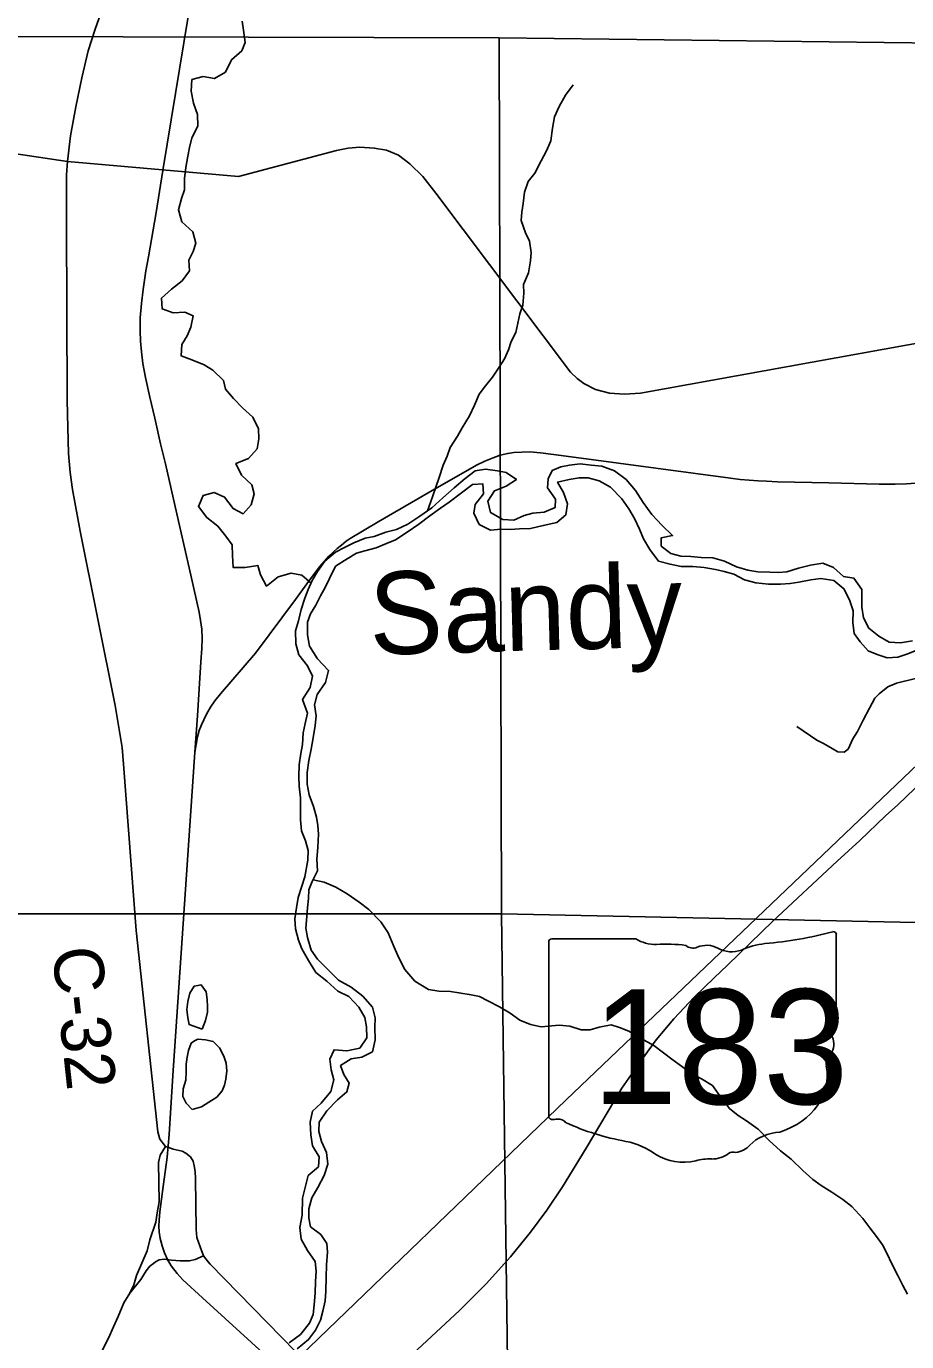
# Model space of a CAD drawing. Extents: x 0 to 34, y 0 to 22.
# Drawn here: x 2.706 to 3.716, y 15.037 to 16.545 of the extents above; entities that cross this region are included whole.
import ezdxf

# ---------------------------------------------------------------- set-up
doc = ezdxf.new("R2010")
doc.units = 0
doc.layers.add('Default', color=7, linetype='Continuous')

msp = doc.modelspace()

# ---------------------------------------------------------------- linework, layer by layer
at = {"layer": 'Default'}
for p, q in [((3.3055, 15.4951), (3.3055, 15.295)), ((3.4053, 15.4986), (3.3088, 15.4986)), ((3.6351, 15.3988), (3.6351, 15.5035)), ((3.6351, 15.3989), (3.6351, 15.3988))]:
    msp.add_line(p, q, dxfattribs=at)
for points in [[(2.7536, 16.3903), (2.7572, 16.4197), (2.7633, 16.4531), (2.77, 16.4862), (2.7773, 16.5171), (2.7854, 16.5419), (2.7952, 16.5699), (2.7994, 16.5866), (2.801, 16.5991), (2.8016, 16.6128), (2.8007, 16.6763), (2.7997, 16.8054), (2.7985, 16.9091), (2.7987, 16.9258), (2.8, 16.9356), (2.8021, 16.9437), (2.8053, 16.952), (2.8092, 16.9585), (2.8142, 16.9649), (2.8306, 16.9836), (2.8489, 17.0057), (2.8565, 17.0154)], [(2.9776, 15.0237), (2.9083, 15.0868), (2.8858, 15.1074), (2.8792, 15.1148), (2.8725, 15.1235), (2.8684, 15.1307), (2.8648, 15.1384), (2.8621, 15.1464), (2.8598, 15.1549), (2.8589, 15.1626), (2.8582, 15.1693), (2.8586, 15.176), (2.8596, 15.1856), (2.8627, 15.2088), (2.8679, 15.2483), (2.8701, 15.2744), (2.8744, 15.342), (2.8871, 15.5273), (2.8995, 15.7129), (2.9027, 15.7545), (2.9065, 15.8165), (2.9078, 15.8316), (2.9079, 15.8433), (2.9075, 15.8537), (2.9062, 15.8638), (2.9044, 15.8735), (2.8951, 15.9157), (2.879, 15.986), (2.8658, 16.0435), (2.8602, 16.0664), (2.8536, 16.096), (2.8481, 16.12), (2.8431, 16.1426), (2.8401, 16.1584), (2.8383, 16.1721), (2.8374, 16.1843), (2.8368, 16.1959), (2.837, 16.2108), (2.8386, 16.2275), (2.8405, 16.2436), (2.8435, 16.2647), (2.8465, 16.281), (2.8552, 16.3316), (2.8628, 16.3799), (2.887, 16.5264), (2.936, 16.8224)], [(3.0328, 15.9067), (3.0221, 15.9157), (3.01, 15.9182), (2.9953, 15.9138), (2.9819, 15.9033), (2.9749, 15.9161), (2.9717, 15.927), (2.9573, 15.9245), (2.9434, 15.9247), (2.9428, 15.9383), (2.9426, 15.9504), (2.9352, 15.9605), (2.926, 15.9721), (2.9133, 15.9818), (2.9037, 15.9945), (2.9091, 16.0071), (2.9219, 16.0107), (2.9337, 16.0053), (2.9434, 15.9921), (2.9552, 15.9863), (2.9641, 15.9966), (2.9677, 16.0092), (2.9649, 16.0194), (2.953, 16.0306), (2.9467, 16.0438), (2.961, 16.0497), (2.971, 16.0608), (2.9731, 16.0722), (2.9725, 16.0836), (2.9662, 16.0971), (2.9543, 16.1079), (2.9439, 16.1184), (2.9347, 16.1292), (2.9323, 16.139), (2.9204, 16.151), (2.9104, 16.1569), (2.8963, 16.1627), (2.8838, 16.1674), (2.8847, 16.1804), (2.891, 16.1903), (2.895, 16.2002), (2.8978, 16.2132), (2.8883, 16.2176), (2.8747, 16.2166), (2.8621, 16.2213), (2.8612, 16.2334), (2.8727, 16.2438), (2.885, 16.2535), (2.8935, 16.265), (2.8929, 16.2772), (2.8977, 16.2871), (2.9009, 16.2966), (2.8973, 16.3094), (2.8847, 16.321), (2.8807, 16.335), (2.8842, 16.3479), (2.8878, 16.3578), (2.8876, 16.3707), (2.8893, 16.3832), (2.8917, 16.3965), (2.8935, 16.4064), (2.8963, 16.4175), (2.9029, 16.4308), (2.9027, 16.4441), (2.8979, 16.4573), (2.8954, 16.4709), (2.8963, 16.4842), (2.9091, 16.4878), (2.922, 16.4854), (2.9347, 16.4928), (2.9417, 16.5069), (2.9536, 16.5173), (2.9572, 16.5269), (2.9555, 16.5409), (2.9538, 16.5511)], [(2.1, 16.5331), (2.1344, 16.5325), (2.2208, 16.5334), (2.2952, 16.5341), (2.3308, 16.5333), (2.3532, 16.5318), (2.3617, 16.531), (2.3692, 16.5283), (2.393, 16.5144), (2.5498, 16.4286), (2.566, 16.4206), (2.5709, 16.418), (2.6047, 16.4125), (2.7536, 16.3903)], [(3.1662, 15.9895), (3.1722, 16.0057), (3.1758, 16.0168), (3.1798, 16.0278), (3.1844, 16.042), (3.1888, 16.0523), (3.1924, 16.0622), (3.2009, 16.0752), (3.206, 16.0848), (3.2145, 16.0985), (3.2203, 16.1108), (3.2258, 16.1234), (3.2328, 16.133), (3.241, 16.143), (3.2487, 16.1545), (3.2546, 16.164), (3.2594, 16.1743), (3.2622, 16.1839), (3.2677, 16.1942), (3.2698, 16.2048), (3.2723, 16.2155), (3.2755, 16.2254), (3.2768, 16.2394), (3.2763, 16.2493), (3.2821, 16.2627), (3.2845, 16.2763), (3.2851, 16.2858), (3.2834, 16.2987), (3.2787, 16.3085), (3.2739, 16.3224), (3.2745, 16.3323), (3.2759, 16.3422), (3.2775, 16.3551), (3.2819, 16.3673), (3.2893, 16.3769), (3.2966, 16.391), (3.3028, 16.4025), (3.3079, 16.414), (3.3096, 16.4284), (3.312, 16.4413), (3.3175, 16.4532), (3.3245, 16.4662), (3.3333, 16.4781)], [(2.7536, 16.3903), (2.9496, 16.3731), (3.0622, 16.4028), (3.0755, 16.4054), (3.0886, 16.4068), (3.1054, 16.4056), (3.1194, 16.4032), (3.1332, 16.3974), (3.1463, 16.3874), (3.161, 16.3732), (3.1758, 16.3541), (3.3304, 16.1487), (3.3378, 16.1413), (3.3458, 16.1357), (3.3589, 16.1287), (3.3749, 16.1245), (3.3922, 16.1234), (3.4105, 16.1244), (3.9144, 16.2154), (3.9245, 16.2165), (3.9335, 16.2176), (4.1665, 16.2407)], [(2.8685, 15.2596), (2.8659, 15.2606), (2.8595, 15.269), (2.8571, 15.2774), (2.8325, 15.5081), (2.8177, 15.6989), (2.8161, 15.7182), (2.8084, 15.7663), (2.7681, 15.9661), (2.7595, 16.014), (2.7566, 16.0335), (2.7547, 16.0552), (2.7538, 16.085), (2.7532, 16.1166), (2.7523, 16.3202), (2.7526, 16.375), (2.7536, 16.3903)], [(2.8995, 15.7129), (2.9025, 15.7305), (2.9047, 15.7377), (2.9072, 15.7441), (2.9098, 15.7499), (2.9131, 15.7565), (2.9177, 15.7645), (2.9227, 15.7718), (2.9292, 15.7795), (2.969, 15.8264), (3.015, 15.8878), (3.0312, 15.9101), (3.0428, 15.9258), (3.0479, 15.9316), (3.0533, 15.9374), (3.0581, 15.942), (3.0628, 15.9462), (3.0678, 15.9503), (3.0733, 15.9547), (3.0778, 15.958), (3.1098, 15.977), (3.167, 16.0101), (3.2225, 16.0418), (3.2323, 16.0466), (3.2415, 16.0504), (3.2496, 16.0534), (3.2583, 16.0554), (3.2655, 16.0564), (3.2745, 16.0569), (3.2838, 16.0571), (3.2958, 16.056), (3.3108, 16.0542), (3.3425, 16.0501), (3.5139, 16.027), (3.5249, 16.0257), (3.5351, 16.0246), (3.5454, 16.0241), (3.555, 16.0235), (3.5677, 16.0229), (3.6264, 16.0217), (3.6842, 16.0203), (3.7025, 16.0202), (3.7156, 16.0206), (3.7263, 16.0214)], [(3.3191, 16.04), (3.3093, 16.0357), (3.3049, 16.0261), (3.304, 16.0159), (3.3133, 16.0028), (3.3127, 15.9933), (3.3003, 15.9882), (3.2871, 15.9868), (3.2773, 15.9844), (3.2653, 15.9788), (3.2528, 15.9798), (3.2387, 15.9875), (3.2355, 16.0007), (3.2432, 16.0126), (3.2567, 16.0177), (3.2683, 16.0255), (3.2564, 16.0337), (3.2466, 16.0354), (3.2329, 16.0374), (3.2209, 16.0353), (3.2097, 16.0268), (3.197, 16.016), (3.184, 16.0044), (3.1713, 15.9932), (3.1575, 15.9835), (3.1437, 15.9741), (3.131, 15.9682), (3.1185, 15.965), (3.1054, 15.9602), (3.0949, 15.9582), (3.0821, 15.953), (3.0712, 15.9475), (3.0607, 15.942), (3.0488, 15.932), (3.0403, 15.9201), (3.0341, 15.9097), (3.0297, 15.8994), (3.0257, 15.8895), (3.0214, 15.8765), (3.0183, 15.8636), (3.0151, 15.8518), (3.0153, 15.837), (3.0189, 15.8246), (3.0286, 15.8118), (3.0345, 15.7998), (3.0317, 15.7869), (3.0232, 15.7731), (3.0288, 15.7576), (3.0263, 15.7458), (3.0239, 15.7348), (3.023, 15.7215), (3.0212, 15.7112), (3.0192, 15.6983), (3.0187, 15.685), (3.0192, 15.6737), (3.0206, 15.6604), (3.0208, 15.6475), (3.0207, 15.635), (3.022, 15.6225), (3.0264, 15.6112), (3.0296, 15.5999), (3.029, 15.5889), (3.0256, 15.5699), (3.0223, 15.5592), (3.018, 15.5459), (3.016, 15.5341), (3.0143, 15.5216), (3.0149, 15.5102), (3.0185, 15.497), (3.0221, 15.4872), (3.0298, 15.4737), (3.0384, 15.4602), (3.051, 15.4501), (3.0637, 15.4386), (3.0763, 15.4324), (3.0878, 15.4204), (3.0945, 15.4084), (3.0965, 15.3978), (3.0967, 15.3853), (3.0886, 15.3734), (3.0739, 15.3702), (3.0592, 15.3714), (3.0545, 15.3607), (3.0558, 15.3486), (3.059, 15.3369), (3.0555, 15.3236), (3.0444, 15.3101), (3.0347, 15.3012), (3.0319, 15.2883), (3.0325, 15.2739), (3.0346, 15.2614), (3.042, 15.2487), (3.0415, 15.2373), (3.0295, 15.2272), (3.0232, 15.2013), (3.0228, 15.1816), (3.02, 15.1675), (3.0217, 15.1543), (3.0287, 15.1411), (3.0376, 15.1284), (3.0386, 15.1174)], [(3.7223, 15.8406), (3.7087, 15.8381), (3.6959, 15.839), (3.684, 15.846), (3.6725, 15.8549), (3.6663, 15.8669), (3.6642, 15.879), (3.6644, 15.8893), (3.6642, 15.8995), (3.6553, 15.9122), (3.6432, 15.9143), (3.632, 15.9247), (3.6195, 15.9295), (3.6056, 15.9273), (3.5916, 15.9237), (3.5785, 15.9197), (3.5687, 15.9187), (3.5588, 15.9193), (3.5452, 15.9195), (3.5335, 15.9216), (3.5206, 15.9255), (3.5068, 15.9317), (3.4935, 15.9357), (3.4803, 15.9362), (3.4682, 15.9371), (3.4569, 15.9377), (3.4455, 15.9406), (3.4344, 15.9491), (3.4342, 15.9586), (3.4474, 15.9611), (3.4355, 15.9726), (3.4235, 15.9853), (3.4135, 15.9992), (3.4049, 16.013), (3.3941, 16.0254), (3.3807, 16.0354), (3.3663, 16.0408), (3.3542, 16.0421), (3.3413, 16.0434), (3.3292, 16.0421), (3.3191, 16.04)], [(2.9993, 14.9996), (3.3253, 15.3142), (3.7288, 15.6994), (3.8497, 15.8071), (3.923, 15.8692), (3.9623, 15.9011), (4.0263, 15.9543), (4.1309, 16.0297)], [(3.2304, 16.009), (3.2212, 15.9967), (3.2195, 15.9868), (3.2257, 15.974), (3.2387, 15.9674), (3.2508, 15.9684), (3.2613, 15.9682), (3.2719, 15.9691), (3.2844, 15.9693), (3.2991, 15.9726), (3.3145, 15.9763), (3.3249, 15.9848), (3.327, 15.9977), (3.3222, 16.0105), (3.3156, 16.0225), (3.3288, 16.0254), (3.3404, 16.0275), (3.3506, 16.0273), (3.3632, 16.0241), (3.3761, 16.0167), (3.3892, 16.0033), (3.3974, 15.9917), (3.4036, 15.9808), (3.4095, 15.9684), (3.4142, 15.9575), (3.4212, 15.9451), (3.4313, 15.932), (3.4445, 15.9284), (3.4574, 15.9256), (3.4707, 15.9258), (3.4835, 15.9245), (3.4964, 15.9221), (3.5067, 15.92), (3.5177, 15.9168), (3.5299, 15.9105), (3.5428, 15.9069), (3.5572, 15.9053), (3.5712, 15.9055), (3.5821, 15.9061), (3.5923, 15.9078), (3.6058, 15.9103), (3.6172, 15.912), (3.6323, 15.9096), (3.6438, 15.9003), (3.6504, 15.8875), (3.6544, 15.8747), (3.6539, 15.8614), (3.6556, 15.8489), (3.6626, 15.8392), (3.6715, 15.8291), (3.6818, 15.8247), (3.6935, 15.8211), (3.7056, 15.8217), (3.7158, 15.8253), (3.7285, 15.8301)], [(3.0171, 15.0283), (3.0301, 15.0391), (3.0379, 15.0499), (3.0437, 15.0614), (3.0462, 15.0716), (3.049, 15.0834), (3.0499, 15.0945), (3.05, 15.1104), (3.0506, 15.1248), (3.0518, 15.1392), (3.0509, 15.1491), (3.0439, 15.1596), (3.0324, 15.1685), (3.0304, 15.1783), (3.0302, 15.1889), (3.0337, 15.2015), (3.0407, 15.2134), (3.048, 15.2271), (3.052, 15.2401), (3.0506, 15.2537), (3.0447, 15.2661), (3.0419, 15.2775), (3.0421, 15.2885), (3.0509, 15.3015), (3.0632, 15.3139), (3.074, 15.3231), (3.0765, 15.333), (3.0703, 15.3432), (3.0667, 15.3533), (3.079, 15.3611), (3.0911, 15.3629), (3.1034, 15.3691), (3.1062, 15.3828), (3.106, 15.3972), (3.1062, 15.4079), (3.1033, 15.4203), (3.0921, 15.433), (3.0787, 15.4434), (3.0642, 15.4511), (3.0519, 15.4638), (3.0404, 15.4754), (3.033, 15.4855), (3.0286, 15.5002), (3.0269, 15.5108), (3.0279, 15.5241), (3.0288, 15.5343), (3.0298, 15.5449), (3.0303, 15.5548), (3.0343, 15.5644), (3.0402, 15.5766), (3.0396, 15.5902), (3.0408, 15.6035), (3.0413, 15.6187), (3.0408, 15.6285), (3.0391, 15.6384), (3.0355, 15.6504), (3.0307, 15.664), (3.0283, 15.6761), (3.0284, 15.6894), (3.0304, 15.7034), (3.0329, 15.7164), (3.0353, 15.7293), (3.0377, 15.7434), (3.0386, 15.7544), (3.0369, 15.7672), (3.0397, 15.779), (3.0493, 15.7925), (3.0529, 15.8066), (3.0402, 15.82), (3.0312, 15.8342), (3.0287, 15.8475), (3.0289, 15.8619), (3.0321, 15.8714), (3.0384, 15.8814), (3.0438, 15.8921), (3.049, 15.9016), (3.0541, 15.912), (3.061, 15.9261), (3.0741, 15.9347), (3.0849, 15.9409), (3.0947, 15.9437), (3.1075, 15.947), (3.1195, 15.9521), (3.1297, 15.9565), (3.1431, 15.965), (3.1566, 15.9744), (3.1689, 15.9837), (3.1812, 15.9926), (3.1913, 15.9996), (3.2054, 16.0101), (3.2178, 16.0197), (3.2298, 16.0207), (3.2304, 16.009)], [(3.8112, 15.8044), (3.8059, 15.8039), (3.792, 15.8039), (3.7672, 15.8039), (3.748, 15.8024), (3.736, 15.8005), (3.7276, 15.7978), (3.7042, 15.792), (3.6942, 15.7876), (3.6843, 15.7795), (3.6794, 15.7746), (3.673, 15.7633), (3.6659, 15.7496), (3.6593, 15.7364), (3.654, 15.7279), (3.6486, 15.7161), (3.644, 15.7126), (3.637, 15.7131), (3.6303, 15.7168), (3.6259, 15.7198), (3.6204, 15.7228), (3.6129, 15.7265), (3.5899, 15.7424)], [(3.0804, 14.9583), (3.2029, 15.0723), (3.2335, 15.1029), (3.2614, 15.134), (3.2843, 15.1621), (3.3033, 15.1875), (3.3213, 15.2141), (3.3483, 15.2584), (3.3893, 15.3275), (3.4105, 15.358), (3.4286, 15.3829), (3.449, 15.4069), (3.4721, 15.4317), (3.495, 15.4541), (3.5104, 15.4683), (3.5624, 15.5191), (3.6359, 15.5876), (3.662, 15.6115), (3.6916, 15.6399), (3.7055, 15.6525), (3.8122, 15.7547)], [(3.0354, 15.5665), (3.048, 15.5635), (3.0613, 15.558), (3.0743, 15.5503), (3.088, 15.5406), (3.0991, 15.5325), (3.113, 15.5183), (3.1211, 15.5055), (3.127, 15.4916), (3.1333, 15.4777), (3.1404, 15.4634), (3.1519, 15.45), (3.1676, 15.4404), (3.1793, 15.4387), (3.1926, 15.4381), (3.2024, 15.4368), (3.2164, 15.4344), (3.2259, 15.4326), (3.2355, 15.4275), (3.2488, 15.4205), (3.261, 15.4135), (3.2721, 15.4053), (3.2843, 15.4006), (3.2968, 15.3978), (3.3172, 15.3997), (3.3297, 15.3984), (3.3426, 15.3944), (3.3528, 15.3942), (3.3633, 15.3974), (3.3769, 15.3999), (3.3864, 15.397), (3.3974, 15.3927), (3.4115, 15.3842), (3.4257, 15.3765), (3.4371, 15.3679), (3.4467, 15.3605), (3.4593, 15.3516), (3.4689, 15.3442), (3.4807, 15.338), (3.493, 15.3306), (3.5034, 15.316), (3.5127, 15.304), (3.5226, 15.2962), (3.5322, 15.2899), (3.5456, 15.2803), (3.5583, 15.2672), (3.5713, 15.2557), (3.5832, 15.246), (3.5967, 15.233), (3.6082, 15.2226), (3.6177, 15.2159), (3.63, 15.2081), (3.6426, 15.1996), (3.6529, 15.1915), (3.6656, 15.178), (3.6737, 15.1672), (3.6811, 15.1574), (3.6881, 15.1477), (3.6935, 15.1372), (3.6982, 15.1266), (3.7057, 15.1127), (3.7115, 15.1011), (3.7166, 15.0913)], [(2.9032, 15.4453), (2.8987, 15.4443), (2.894, 15.4363), (2.8915, 15.4268), (2.8905, 15.4177), (2.8914, 15.4082), (2.893, 15.4003), (2.9082, 15.3952)], [(2.9082, 15.3952), (2.9119, 15.4051), (2.914, 15.4146), (2.9143, 15.4207), (2.9137, 15.429), (2.9125, 15.4377), (2.9067, 15.446), (2.9032, 15.4453)], [(2.8994, 15.3815), (2.8953, 15.3791), (2.8924, 15.3707), (2.891, 15.3631), (2.8896, 15.3551), (2.8898, 15.3464), (2.8892, 15.3365), (2.8863, 15.3266), (2.8857, 15.3179), (2.8896, 15.31), (2.8965, 15.3029)], [(2.8965, 15.3029), (2.9074, 15.3061), (2.9157, 15.3112), (2.9247, 15.317), (2.931, 15.3243), (2.9335, 15.3308), (2.9353, 15.3376), (2.9363, 15.3471), (2.9357, 15.3562), (2.9329, 15.3641), (2.9279, 15.3735), (2.9206, 15.381), (2.9119, 15.3828), (2.9031, 15.3837), (2.8994, 15.3815)], [(2.8659, 15.2606), (2.8597, 15.2507), (2.8578, 15.2423), (2.8586, 15.1969), (2.8563, 15.1844), (2.855, 15.1738), (2.8481, 15.1534), (2.8449, 15.1409), (2.8326, 15.1127), (2.8296, 15.1019), (2.8252, 15.0921)], [(3.0804, 14.9583), (2.9171, 15.1257), (2.9148, 15.1282), (2.9096, 15.1349), (2.9058, 15.1453), (2.9019, 15.1561), (2.901, 15.1653), (2.9004, 15.2236), (2.8999, 15.2317), (2.8989, 15.2384), (2.8976, 15.2437), (2.8947, 15.2486), (2.8894, 15.253), (2.8851, 15.2552), (2.8746, 15.2575), (2.8685, 15.2596)], [(2.8252, 15.0921), (2.8375, 15.1078), (2.8439, 15.1178), (2.8481, 15.1231), (2.8521, 15.1264), (2.8545, 15.1281), (2.8589, 15.1304), (2.8644, 15.1313), (2.8728, 15.1303), (2.8828, 15.1292), (2.8935, 15.1295), (2.9001, 15.1309), (2.9096, 15.1349)], [(3.0386, 15.1174), (3.038, 15.1056), (3.0375, 15.0924), (3.0366, 15.0787), (3.0353, 15.0677), (3.0309, 15.0577), (3.0206, 15.0447), (3.0079, 15.0354)], [(2.8252, 15.0921), (2.8181, 15.0811), (2.8118, 15.0654), (2.8065, 15.0538), (2.8006, 15.0405), (2.7873, 15.0143), (2.7806, 15.0003), (2.7715, 14.9855), (2.7495, 14.9487), (2.7235, 14.9232)]]:
    msp.add_lwpolyline(points, dxfattribs=at)
for points in [[(2.2428, 16.5348), (3.2485, 16.532), (3.2514, 15.5272), (2.2442, 15.5273)], [(3.2485, 16.532), (4.2574, 16.5198), (4.2566, 15.5062), (3.2514, 15.5272)], [(3.2514, 15.5272), (3.2648, 14.5009), (2.2573, 14.5177), (2.2442, 15.5273)], [(4.2566, 15.5062), (4.2629, 14.5006), (3.2648, 14.5009), (3.2514, 15.5272)]]:
    msp.add_lwpolyline(points, close=True, dxfattribs=at)
for centre, major_axis, start_param, end_param in [((3.3093, 15.4956), (0.00382, 0), 1.712693, 3.28349), ((3.4283, 15.5218), (0.037, 0), 4.042523, 4.731795), ((3.5177, 15.7714), (0.3495, 0), 4.814394, 5.042369), ((3.6315, 15.504), (0.00367, 0), 6.141152, 7.989035), ((3.4406, 15.3862), (0.133, 0), 1.404758, 1.657858), ((3.4707, 15.4966), (0.0107, 0), 3.836095, 5.185415), ((3.4864, 15.4735), (0.0222, 0), 0.950623, 2.079405), ((3.5151, 15.5052), (0.0267, 0), 4.081561, 5.145723), ((3.5623, 15.4374), (0.0703, 0), 1.699011, 2.107814), ((3.6343, 15.3912), (0.00568, 0), 1.883978, 3.671073), ((3.5981, 15.3779), (0.0341, 0), 5.934695, 6.695948), ((3.6312, 15.3984), (0.00393, 0), 5.05454, 6.418171), ((3.6483, 15.355), (0.0248, 0), 2.387724, 3.262537), ((3.5373, 15.3417), (0.0874, 0), 5.101752, 6.440018), ((3.3093, 15.2946), (0.00385, 0), 3.00124, 4.508301), ((3.3099, 15.315), (0.0294, 0), 4.665946, 4.897461), ((3.3159, 15.2835), (0.0106, 0), 0.519207, 1.627899), ((3.4498, 15.4633), (0.2524, 0), 4.195997, 4.488961), ((3.5741, 15.2388), (0.0479, 0), 1.647645, 2.488434), ((3.3745, 15.2051), (0.079, 0), 0.823519, 1.323587), ((3.5167, 15.2481), (0.00752, 0), 1.147584, 2.315152), ((3.5135, 15.2756), (0.0282, 0), 4.937069, 5.64225), ((3.4599, 15.2825), (0.0501, 0), 4.026481, 4.996735), ((3.4889, 15.2133), (0.0412, 0), 1.495662, 1.94098), ((3.4925, 15.2675), (0.0267, 0), 4.691044, 5.507374)]:
    msp.add_ellipse(centre, major_axis=major_axis, ratio=0.8, start_param=start_param, end_param=end_param, dxfattribs=at)

# ---------------------------------------------------------------- texts
for s, height, rotation, p in [('Sandy', 0.09472, 1.5445, (3.1006, 15.8244)), ('C-32', 0.05682, 276.1891, (2.7358, 15.4871)), ('183', 0.000189, 0, (3.3998, 15.368))]:
    msp.add_text(s, height=height, rotation=rotation, dxfattribs=at).set_placement(p)
for s, height, p in [('183', 0.13184, (3.355, 15.3091)), ('s', 0.000189, (3.4666, 15.3818)), ('r', 0.000189, (3.4666, 15.3818))]:
    msp.add_text(s, height=height, dxfattribs=at).set_placement(p)

doc.saveas('drawing.dxf')
